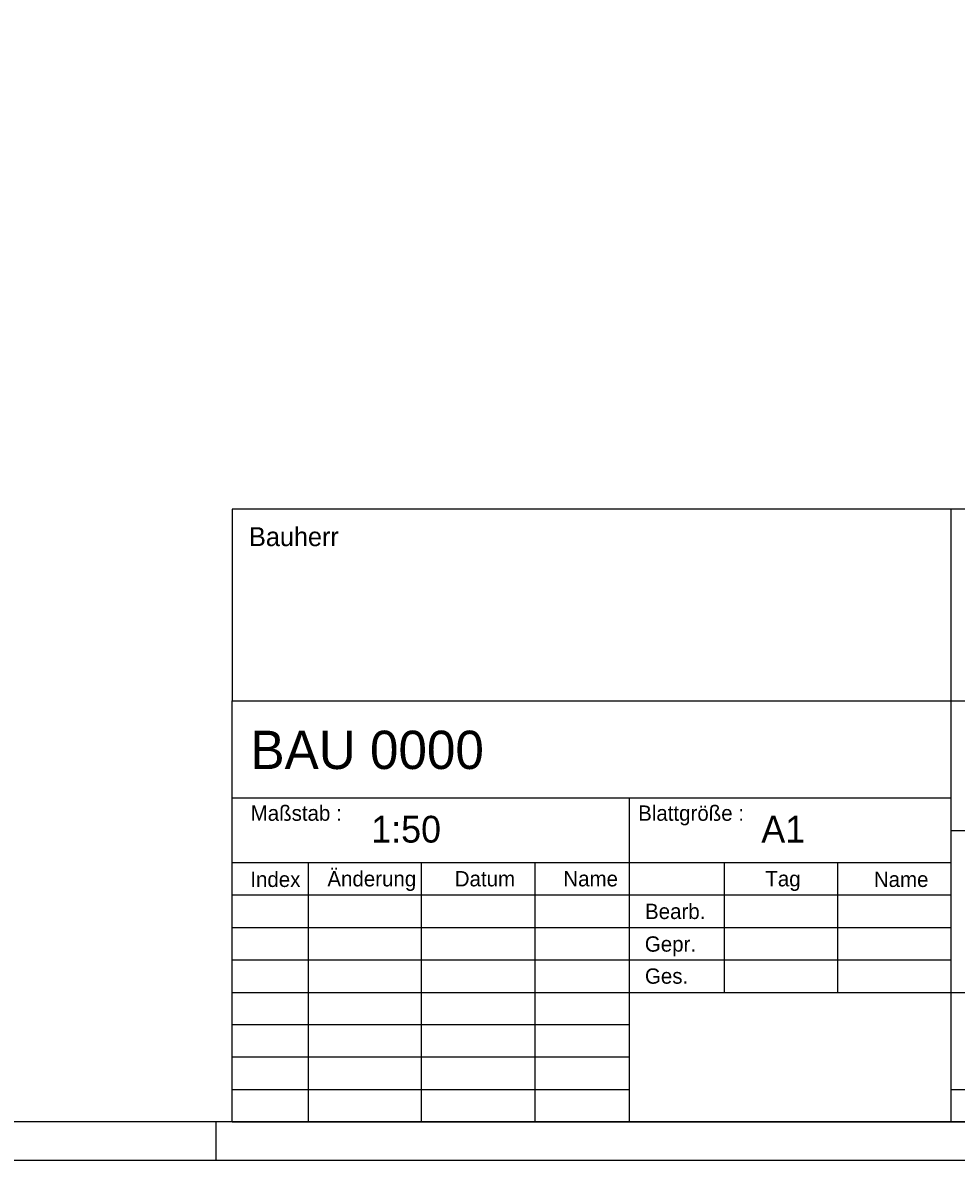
# Model space of a CAD drawing. Extents: x 0 to 42.1, y 0 to 29.7.
# Drawn here: x 31.54 to 37.63, y 0 to 7.43 of the extents above; entities that cross this region are included whole.
import ezdxf

# ---------------------------------------------------------------- set-up
doc = ezdxf.new("R2010")
doc.units = 0
doc.layers.add('90_Plankopf', color=7, linetype='Continuous')

msp = doc.modelspace()

# ---------------------------------------------------------------- linework, layer by layer
at = {"layer": '90_Plankopf'}
for p, q in [((41.8, 4.2495), (32.906, 4.2495)), ((32.906, 4.2495), (32.906, 2.9995)), ((37.6001, 2.9995), (37.6001, 4.2495)), ((32.906, 2.9995), (41.8, 2.9995)), ((32.906, 0.25), (32.906, 2.9995)), ((32.906, 2.9995), (41.8, 2.9995)), ((37.6001, 0.25), (37.6001, 2.9995)), ((32.906, 2.365), (37.6001, 2.365)), ((35.5001, 0.25), (35.5001, 2.365)), ((37.6001, 2.1535), (41.8, 2.1535)), ((32.906, 1.9435), (37.6001, 1.9435)), ((33.4001, 1.942), (33.4001, 0.25)), ((34.1413, 0.25), (34.1413, 1.942)), ((34.8825, 0.25), (34.8825, 1.942)), ((36.1177, 1.942), (36.1177, 1.096)), ((36.8589, 1.096), (36.8589, 1.942)), ((32.906, 1.7315), (37.6001, 1.7315)), ((32.906, 1.519), (37.6001, 1.519)), ((32.906, 1.3075), (37.6001, 1.3075)), ((32.906, 1.096), (37.6001, 1.096)), ((32.906, 1.096), (37.6001, 1.096)), ((35.5001, 1.096), (37.6001, 1.096)), ((37.6001, 1.096), (41.8, 1.096)), ((35.5001, 0.8845), (32.906, 0.8845)), ((35.5001, 0.673), (32.906, 0.673)), ((32.906, 0.4615), (35.5001, 0.4615)), ((37.6001, 0.4615), (41.8, 0.4615)), ((32.8, 0), (32.8, 0.25)), ((41.8, 0.25), (32.906, 0.25)), ((32.906, 0.25), (35.5001, 0.25)), ((33.49, 0.25), (41.8, 0.25)), ((33.49, 0.25), (41.8, 0.25))]:
    msp.add_line(p, q, dxfattribs=at)
for points in [[(0, 0), (42.05, 0), (42.05, 29.7), (0, 29.7)], [(1.25, 29.45), (41.8, 29.45), (41.8, 0.25), (1.25, 0.25)]]:
    msp.add_lwpolyline(points, close=True, dxfattribs=at)

# ---------------------------------------------------------------- texts
for s, height, p in [('Bauherr', 0.12318, (33.0152, 4.0088)), ('BAU 0000      ', 0.25, (33.0245, 2.5538)), ('Maßstab :', 0.1, (33.0258, 2.2158)), ('Blattgröße :', 0.099995, (35.5558, 2.2158)), ('1:50     ', 0.175, (33.8131, 2.0734)), ('A1       ', 0.175, (36.36, 2.0734)), ('Index', 0.1, (33.0235, 1.7837)), ('Änderung', 0.1, (33.5267, 1.7875)), ('Datum', 0.1, (34.3584, 1.7875)), ('Name', 0.1, (35.0674, 1.7875)), ('Tag', 0.1, (36.3862, 1.7875)), ('Name', 0.1, (37.0946, 1.7837)), ('Bearb.', 0.1, (35.6007, 1.5745)), ('Gepr.', 0.1, (35.5995, 1.3615)), ('Ges.', 0.1, (35.6002, 1.1523))]:
    msp.add_text(s, height=height, dxfattribs=at).set_placement(p)

doc.saveas('drawing.dxf')
